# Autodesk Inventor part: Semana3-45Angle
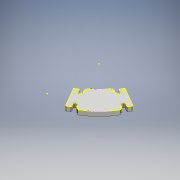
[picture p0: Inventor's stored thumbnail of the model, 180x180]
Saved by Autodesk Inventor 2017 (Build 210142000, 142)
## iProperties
Created: 2017-02
Part Number: Semana3-45Angle
Material: Generic
Document SubType Name: Modeling
Designer: diego
Density: 1 g/cm^3
Appearance: Default
Author: diego
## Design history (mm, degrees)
derived "Semana3-triangulo.ipt"
sketch "Sketch1"
  geometry: L1 (21.25, 5.694)-(20.284, 5.435) reference; L2 (20.284, -5.435)-(21.25, -5.694) reference; L3 (21.604, -6.306)-(21.539, -6.548) reference; L4 (21.893, -7.16)-(24.549, -7.872) reference; L5 (24.903, -8.484)-(24.579, -9.692) reference; L6 (23.967, -10.045)-(21.31, -9.334) reference; L7 (20.698, -9.687)-(20.175, -11.638) reference; L8 (20.529, -12.251)-(34.052, -15.874) reference; L9 (34.664, -15.521)-(35.187, -13.569) reference; L10 (34.833, -12.957)-(32.177, -12.245) reference; L11 (31.824, -11.633)-(32.147, -10.426) reference; L12 (32.759, -10.072)-(35.416, -10.784) reference; L13 (36.028, -10.43)-(36.093, -10.189) reference; L14 (36.705, -9.835)-(37.671, -10.094) reference; L15 (37.671, 10.094)-(36.705, 9.835) reference; L16 (36.093, 10.189)-(36.028, 10.43) reference; L17 (35.416, 10.784)-(32.759, 10.072) reference; L18 (32.147, 10.426)-(31.824, 11.633) reference; L19 (32.177, 12.245)-(34.833, 12.957) reference; L20 (35.187, 13.569)-(34.664, 15.521) reference; L21 (34.052, 15.874)-(20.529, 12.251) reference; L22 (20.175, 11.638)-(20.698, 9.687) reference; L23 (21.31, 9.334)-(23.967, 10.045) reference; L24 (24.579, 9.692)-(24.903, 8.484) reference; L25 (24.549, 7.872)-(21.893, 7.16) reference; L26 (21.539, 6.548)-(21.604, 6.306) reference; A1 r 21 centre (0, 0) between (20.284, -5.435) and (20.284, 5.435) reference; A2 r 0.5 centre (21.121, -6.177) between (21.604, -6.306) and (21.25, -5.694) reference; A3 r 0.5 centre (22.022, -6.677) between (21.539, -6.548) and (21.893, -7.16) reference; A4 r 0.5 centre (24.42, -8.355) between (24.903, -8.484) and (24.549, -7.872) reference; A5 r 0.5 centre (24.096, -9.562) between (23.967, -10.045) and (24.579, -9.692) reference; A6 r 0.5 centre (21.181, -9.817) between (21.31, -9.334) and (20.698, -9.687) reference; A7 r 0.5 centre (20.658, -11.768) between (20.175, -11.638) and (20.529, -12.251) reference; A8 r 0.5 centre (34.181, -15.391) between (34.052, -15.874) and (34.664, -15.521) reference; A9 r 0.5 centre (34.704, -13.44) between (35.187, -13.569) and (34.833, -12.957) reference; A10 r 0.5 centre (32.307, -11.762) between (31.824, -11.633) and (32.177, -12.245) reference; A11 r 0.5 centre (32.63, -10.555) between (32.759, -10.072) and (32.147, -10.426) reference; A12 r 0.5 centre (35.545, -10.301) between (35.416, -10.784) and (36.028, -10.43) reference; A13 r 0.5 centre (36.576, -10.318) between (36.705, -9.835) and (36.093, -10.189) reference; A14 r 39 centre (0, 0) between (37.671, -10.094) and (37.671, 10.094) reference; A15 r 0.5 centre (36.576, 10.318) between (36.093, 10.189) and (36.705, 9.835) reference; A16 r 0.5 centre (35.545, 10.301) between (36.028, 10.43) and (35.416, 10.784) reference; A17 r 0.5 centre (32.63, 10.555) between (32.147, 10.426) and (32.759, 10.072) reference; A18 r 0.5 centre (32.307, 11.762) between (32.177, 12.245) and (31.824, 11.633) reference; A19 r 0.5 centre (34.704, 13.44) between (34.833, 12.957) and (35.187, 13.569) reference; A20 r 0.5 centre (34.181, 15.391) between (34.664, 15.521) and (34.052, 15.874) reference; A21 r 0.5 centre (20.658, 11.768) between (20.529, 12.251) and (20.175, 11.638) reference; A22 r 0.5 centre (21.181, 9.817) between (20.698, 9.687) and (21.31, 9.334) reference; A23 r 0.5 centre (24.096, 9.562) between (24.579, 9.692) and (23.967, 10.045) reference; A24 r 0.5 centre (24.42, 8.355) between (24.549, 7.872) and (24.903, 8.484) reference; A25 r 0.5 centre (22.022, 6.677) between (21.893, 7.16) and (21.539, 6.548) reference; A26 r 0.5 centre (21.121, 6.177) between (21.25, 5.694) and (21.604, 6.306) reference; 1 further point
  node "Projected Loop1"
feature "45Angle::Semana3-triangulo.ipt" dims "d1" = 10
tag "TaggingFeature2"
body "Solid1"
body "Solid2"
